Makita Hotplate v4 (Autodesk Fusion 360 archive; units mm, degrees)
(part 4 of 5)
sketch "Sketch1" plane through (0, 0, 0) normal (0, 0, 1) x axis (1, 0, 0)
  line L1 (20, 0) -> (0, 0)
  line L2 (20, 73) -> (20, 0)
  line L3 (0, 73) -> (20, 73)
  line L4 (0, 0) -> (0, 73)
  line L5 (3, 4) -> (3, 69)
  line L6 (0, 36.5) -> (3, 36.5)
  line L7 (0, 69) -> (3, 69)
  line L8 (0, 98) -> (0, 73)
  line L9 (-20, 98) -> (0, 98)
  line L10 (-20, 156) -> (-20, 98)
  line L11 (20, 156) -> (-20, 156)
  line L12 (20, 73) -> (20, 156)
  line L13 (-9, 155.75) -> (-18, 155.75)
  line L14 (-9, 98.25) -> (-9, 155.75)
  line L15 (-18, 98.25) -> (-9, 98.25)
  line L16 (-18, 155.75) -> (-18, 98.25)
  line L17 (-11, 146) -> (-16, 146)
  line L18 (-11, 108) -> (-11, 146)
  line L19 (-16, 108) -> (-11, 108)
  line L20 (-16, 146) -> (-16, 108)
  line L21 (-9, 98.25) -> (-18, 155.75)
  line L22 (-11, 146) -> (-16, 108)
  circle C1 centre (3, 4) radius 1.625
  circle C2 centre (3, 69) radius 1.625
  circle C3 centre (3, 69) radius 3
  circle C4 centre (10, 84.5) radius 5
  point P1 (0, 0)
  point P2 (0, 0)
  point P7 (3, 4)
  point P8 (3, 4)
  point P6 (3, 69)
  point P9 (3, 69)
  point P10 (3, 36.5)
  point P11 (0, 36.5)
  point P12 (3, 69)
  point P13 (0, 69)
  point P14 (1.375, 69)
  point P4 (20, 73)
  point P20 (20, 73)
  point P5 (0, 73)
  point P16 (0, 98)
  point P3 (20, 0)
  point P17 (-20, 98)
  point P18 (-20, 156)
  point P21 (-18, 155.75)
  point P22 (-9, 155.75)
  point P15 (3, 69)
  point P25 (10, 84.5)
  point P26 (-16, 146)
  point P27 (-11, 146)
  point P29 (-16, 108)
  horizontal L1
  vertical L2
  horizontal L3
  vertical L4
  coincident P1 P2
  vertical L5
  coincident P7 P8
  coincident P6 P9
  equal C1 C2
  midpoint L5 P10
  midpoint L4 P11
  horizontal L6
  coincident P9 P12
  coincident L4 P13
  perpendicular L4 L7
  coincident C2 P14
  coincident L7 P14
  concentric C2 C3
  perpendicular L3 L8
  perpendicular L8 L9
  perpendicular L9 L10
  perpendicular L10 L11
  perpendicular L3 L12
  coincident P4 P20
  horizontal L13
  vertical L14
  horizontal L15
  vertical L16
  horizontal L17
  vertical L18
  horizontal L19
  vertical L20
  midpoint L21 L22
  dimension "d1" distance P2 P5 = 73
  dimension "d2" diameter C2 = 3.25
  dimension "d3" distance P6 P7 = 65
  dimension "d4" distance P10 P11 = 3
  dimension "d5" distance L4 P14 = 1.375
  dimension "d6" diameter C3 = 6
  dimension "d13" distance P5 P16 = 25 (= "23.5 mm + 1.5 mm")
  dimension "d14" distance P2 P3 = 20
  dimension "d15" distance P17 P18 = 58
  dimension "d16" distance P16 P17 = 20
  dimension "d17" distance P18 L16 = 2
  dimension "d18" distance P21 P22 = 9
  dimension "d19" distance P18 L13 = 0.25
  dimension "d20" distance P17 L15 = 0.25
  dimension "d21" diameter C4 = 10
  dimension "d22" distance P15 P25 = 15.5
  dimension "d23" distance P15 P25 = 7
  dimension "d24" distance P26 P27 = 5
  dimension "d25" distance P26 P29 = 38
extrude "Extrude1" new body sketch "Sketch1" profile of L1 L2 L4 C1 C2 L8 L9 L10 L11 L12 L13 L14 L15 L16 C4 L17 L18 L19 L20 against normal blind 1.6
extrude "Extrude2" add sketch "Sketch1" profile of L13 L14 L15 L16 L17 L18 L19 L20 along normal blind 25
extrude "Extrude3" add sketch "Sketch1" profile of L17 L18 L19 L20 against normal blind 4.5
component_insert "Component Insert" sketch "Sketch1"
joint "Assemble1" sketch "Sketch1" alignAngle 90 alignOffsetX 0 alignOffsetY 0 alignOffsetZ 0.7
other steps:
joint_origin "JointOrigin2" sketch "Sketch1"

design "M5x25-FHCS"
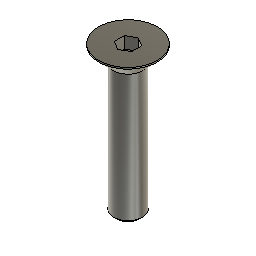
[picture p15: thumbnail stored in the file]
sketch "Sketch1" plane through (0, 0, 0) normal (0, 1, 0) x axis (1, 0, 0)
  line L1 (0, 25) -> (0, 0)
  line L2 (1.95, 25) -> (0, 25)
  line L3 (2.45, 24.5) -> (1.95, 25)
  line L4 (2.45, 2.8) -> (2.45, 24.5)
  line L5 (5, 0.25) -> (2.45, 2.8)
  line L6 (5, 0) -> (5, 0.25)
  line L7 (0, 0) -> (5, 0)
  point P1 (0, 0)
  point P2 (0, 0)
  point P9 (0, 0)
  point P3 (0, 25)
  point P4 (1.95, 25)
  point P8 (5, 0)
  point P7 (5, 0.25)
  coincident P1 P2
  vertical L1
  perpendicular L1 L2
  perpendicular L2 L4
  parallel L3 L5
  parallel L4 L6
  perpendicular L6 L7
  coincident P1 P9
  dimension "d1" distance P3 L4 = 2.45 (= "( 4.9 / 2 ) * 1 mm")
  dimension "d3" angle L2 L3 = 45
  dimension "d5" distance P4 L4 = 0.5
  dimension "d6" distance P2 P3 = 25
  dimension "d7" distance P8 P9 = 5 (= "( 10 / 2 ) * 1 mm")
  dimension "d9" distance P7 P8 = 0.25
revolve "Revolve1" sketch "Sketch1" AlongAngle 360
sketch "Sketch2" plane through (0, 0, 0) normal (0, 0, 1) x axis (-1, 0, 0)
  line L1 (0, -1.7321) -> (-1.5, -0.866)
  line L2 (1.5, -0.866) -> (0, -1.7321)
  line L3 (1.5, 0.866) -> (1.5, -0.866)
  line L4 (0, 1.7321) -> (1.5, 0.866)
  line L5 (-1.5, 0.866) -> (0, 1.7321)
  line L6 (-1.5, -0.866) -> (-1.5, 0.866)
  circle C1 centre (0, 0) radius 5
  point P1 (0, 0)
  point P9 (0, 0)
  coincident P1 P9
  vertical L6
  dimension "d12" distance L3 L6 = 3
extrude "Extrude1" cut sketch "Sketch2" profile of L1 L2 L3 L4 L5 L6 against normal blind 2

design "M4x14-FHCS"
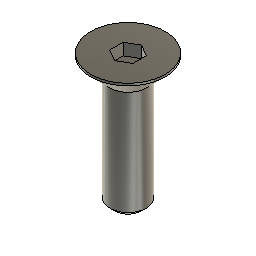
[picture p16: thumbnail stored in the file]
sketch "Sketch1" plane through (0, 0, 0) normal (0, 1, 0) x axis (1, 0, 0)
  line L1 (0, 14) -> (0, 0)
  line L2 (1.45, 14) -> (0, 14)
  line L3 (1.95, 13.5) -> (1.45, 14)
  line L4 (1.95, 2.3) -> (1.95, 13.5)
  line L5 (4, 0.25) -> (1.95, 2.3)
  line L6 (4, 0) -> (4, 0.25)
  line L7 (0, 0) -> (4, 0)
  point P1 (0, 0)
  point P2 (0, 0)
  point P9 (0, 0)
  point P3 (0, 14)
  point P4 (1.45, 14)
  point P8 (4, 0)
  point P7 (4, 0.25)
  coincident P1 P2
  vertical L1
  perpendicular L1 L2
  perpendicular L2 L4
  parallel L3 L5
  parallel L4 L6
  perpendicular L6 L7
  coincident P1 P9
  dimension "d1" distance P3 L4 = 1.95 (= "( 3.9 / 2 ) * 1 mm")
  dimension "d3" angle L2 L3 = 45
  dimension "d5" distance P4 L4 = 0.5
  dimension "d6" distance P2 P3 = 14
  dimension "d7" distance P8 P9 = 4 (= "( 8 / 2 ) * 1 mm")
  dimension "d9" distance P7 P8 = 0.25
revolve "Revolve1" sketch "Sketch1" AlongAngle 360
sketch "Sketch2" plane through (0, 0, 0) normal (0, 0, 1) x axis (-1, 0, 0)
  line L1 (0, -1.4434) -> (-1.25, -0.7217)
  line L2 (1.25, -0.7217) -> (0, -1.4434)
  line L3 (1.25, 0.7217) -> (1.25, -0.7217)
  line L4 (0, 1.4434) -> (1.25, 0.7217)
  line L5 (-1.25, 0.7217) -> (0, 1.4434)
  line L6 (-1.25, -0.7217) -> (-1.25, 0.7217)
  circle C1 centre (0, 0) radius 4
  point P1 (0, 0)
  point P9 (0, 0)
  coincident P1 P9
  vertical L6
  dimension "d12" distance L3 L6 = 2.5
extrude "Extrude1" cut sketch "Sketch2" profile of L1 L2 L3 L4 L5 L6 against normal blind 1.26

design "M5 Nylock"
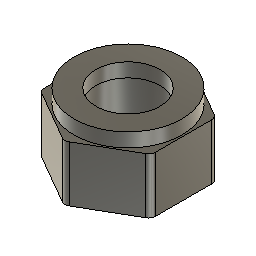
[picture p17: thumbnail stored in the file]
sketch "Sketch1" plane through (0, 0, 0) normal (0, 0, 1) x axis (1, 0, 0)
  line L1 (0, 4.6188) -> (4, 2.3094)
  line L2 (-4, 2.3094) -> (0, 4.6188)
  line L3 (-4, -2.3094) -> (-4, 2.3094)
  line L4 (0, -4.6188) -> (-4, -2.3094)
  line L5 (4, -2.3094) -> (0, -4.6188)
  line L6 (4, 2.3094) -> (4, -2.3094)
  circle C1 centre (0, 0) radius 2.55
  circle C2 centre (0, 0) radius 3.875
  circle C3 centre (0, 0) radius 2.3
  point P1 (0, 0)
  point P8 (0, 0)
  point P9 (0, 0)
  point P4 (-4, 2.3094)
  coincident P1 P8
  vertical L6
  coincident P8 P9
  concentric C1 C2
  concentric C1 C3
  dimension "d1" distance P4 L6 = 8
  dimension "d2" diameter C1 = 5.1
  dimension "d5" diameter C2 = 7.75
  dimension "d9" distance C1 C3 = 0.25
extrude "Extrude1" new body sketch "Sketch1" profile of L1 L2 L3 L4 L5 L6 C1 along normal blind 4
extrude "Extrude2" sketch "Sketch1" profile of C1 C2 C3 blind 1
fillet "Fillet1" radius 0.5

design "Servo Arm 25T"
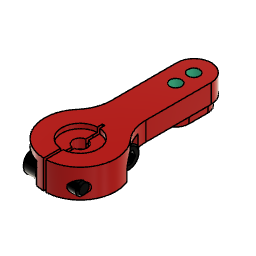
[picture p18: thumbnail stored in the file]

design "M3 Nylock"
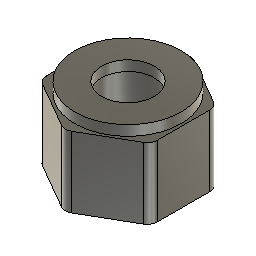
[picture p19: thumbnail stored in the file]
sketch "Sketch1" plane through (0, 0, 0) normal (0, 0, 1) x axis (1, 0, 0)
  line L1 (0, 3.1754) -> (2.75, 1.5877)
  line L2 (-2.75, 1.5877) -> (0, 3.1754)
  line L3 (-2.75, -1.5877) -> (-2.75, 1.5877)
  line L4 (0, -3.1754) -> (-2.75, -1.5877)
  line L5 (2.75, -1.5877) -> (0, -3.1754)
  line L6 (2.75, 1.5877) -> (2.75, -1.5877)
  circle C1 centre (0, 0) radius 1.55
  circle C2 centre (0, 0) radius 2.625
  circle C3 centre (0, 0) radius 1.3
  point P1 (0, 0)
  point P8 (0, 0)
  point P9 (0, 0)
  point P4 (-2.75, 1.5877)
  coincident P1 P8
  vertical L6
  coincident P8 P9
  concentric C1 C2
  concentric C1 C3
  dimension "d1" distance P4 L6 = 5.5
  dimension "d2" diameter C1 = 3.1
  dimension "d5" diameter C2 = 5.25
  dimension "d9" distance C1 C3 = 0.25
extrude "Extrude1" new body sketch "Sketch1" profile of L1 L2 L3 L4 L5 L6 C1 C2 along normal blind 3.5
extrude "Extrude2" sketch "Sketch1" profile of C1 C2 C3 blind 0.5
fillet "Fillet1" radius 0.5

design "Hotplate Pushrod"
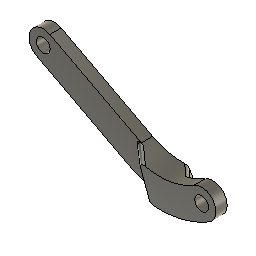
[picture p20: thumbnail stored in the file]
sketch "Sketch1" plane through (0, 0, 0) normal (0, 1, 0) x axis (1, 0, 0)
  line L1 (57.4992, 15.3) -> (0, 0)
  line L2 (43.3571, -7.7) -> (57.4992, 15.3)
  line L3 (43.3571, 19.3) -> (43.3571, -7.7)
  line L4 (30.7869, 16.1954) -> (0, 0)
  line L5 (-2.2347, 4.2481) -> (2.2347, -4.2481)
  line L6 (33.0216, 11.9473) -> (2.2347, -4.2481)
  line L7 (-2.2347, 4.2481) -> (28.5522, 20.4435)
  line L8 (33.0216, 11.9473) -> (28.5522, 20.4435)
  line L9 (35.4522, 23.1018) -> (30.8558, 10.808)
  line L10 (54.6732, 22.0184) -> (49.3571, 13.6738)
  circle C1 centre (0, 0) radius 1.625
  circle C2 centre (57.4992, 15.3) radius 1.625
  arc A1 centre (43.3571, -7.7) radius 27 clockwise from (43.3571, 19.3) to (57.4992, 15.3)
  arc A2 centre (43.3571, -7.7) radius 27 clockwise from (30.7869, 16.1954) to (43.3571, 19.3)
  arc A3 centre (43.3571, -7.7) radius 22.2 clockwise from (33.0216, 11.9473) to (54.9851, 11.2111)
  arc A4 centre (57.4992, 15.3) radius 4.8 clockwise from (60.0134, 19.3889) to (54.9851, 11.2111)
  arc A5 centre (43.3571, -7.7) radius 31.8 clockwise from (28.5522, 20.4435) to (60.0134, 19.3889)
  arc A6 centre (43.3571, -7.7) radius 27 clockwise from (30.7869, 16.1954) to (57.4992, 15.3)
  circle C3 centre (57.4992, 15.3) radius 2.3
  arc A7 centre (0, 0) radius 4.8 clockwise from (2.2347, -4.2481) to (-2.2347, 4.2481)
  circle C4 centre (0, 0) radius 2.3
  point P1 (0, 0)
  point P2 (0, 0)
  point P3 (57.4992, 15.3)
  point P5 (57.4992, 15.3)
  point P4 (0, 0)
  point P7 (57.4992, 15.3)
  point P9 (57.4992, 15.3)
  point P6 (43.3571, -7.7)
  point P10 (43.3571, -7.7)
  point P11 (43.3571, -7.7)
  point P19 (43.3571, -7.7)
  point P12 (30.7869, 16.1954)
  point P17 (30.7869, 16.1954)
  point P21 (0, 0)
  point P28 (54.6732, 22.0184)
  point P27 (49.3571, 13.6738)
  point P26 (35.4522, 23.1018)
  point P25 (30.8558, 10.808)
  point P8 (43.3571, 19.3)
  point P20 (57.4992, 15.3)
  point P24 (0, 0)
  point P16 (28.5522, 20.4435)
  coincident P1 P2
  equal C1 C2
  coincident P3 P5
  coincident P1 P4
  coincident P3 P7
  coincident P5 P9
  coincident P6 P10
  vertical L3
  coincident P6 P11
  tangent A2 L4
  tangent A3 A4
  tangent A4 A5
  coincident P6 P19
  coincident P12 P17
  concentric C2 C3
  coincident P1 P21
  coincident P2 L5
  perpendicular L4 L5
  equal A4 A7
  coincident P17 L8
  perpendicular L4 L8
  concentric C1 C4
  equal C3 C4
  coincident A5 P28
  coincident A3 P27
  coincident A5 P26
  coincident L6 P25
  dimension "d1" diameter C1 = 3.25
  dimension "d2" distance P4 P5 = 59.5 (= "56.5 mm + 3 mm")
  dimension "d6" distance P8 P10 = 27
  dimension "d7" = 31.6
  dimension "d8" diameter C3 = 4.6
  dimension "d9" distance A4 C3 = 2.5
  dimension "d10" distance P20 P24 = 15.3
  dimension "d19" distance P11 P20 = 23
  dimension "d29" angle L3 L10 = 32.5
  dimension "d30" distance L3 P27 = 6
  dimension "d38" distance P16 P26 = 6.9
  dimension "d40" angle L9 L10 = 12
extrude "Extrude4" new body sketch "Sketch1" profile of A3 A4 A5 C3 L9 L10 along normal blind 3.8 bodies "HP Pushrod"
extrude "Extrude5" new body sketch "Sketch1" profile of A3 A5 A7 L6 L7 C4 L9 L10 blind 3.8 from offset 4.2 (= "6.9 mm - 1.2 mm - 1.5 mm")
extrude "Extrude6" add sketch "Sketch1" profile of A3 A5 L6 L7 L9 L10 to an object
chamfer "Chamfer3" distance 4.2
chamfer "Chamfer4" distance 4.2
fillet "Fillet1" radius 1
named bodies: "HP Pushrod"

design "Hotplate Toolchanger" references "M5x25-FHCS", "Servo Standard", "M3x25-FHCS", "Hotplate Tool Template", "6806 Bearing", "PCB Blade Head", "Servo Arm 25T", "3.2x4.5x4mm Unthreaded Spacer", "M3x20-FHCS", "M4x14-FHCS", "M3 Nylock", "Hotplate Pushrod", "M5 Nylock", "M3x14-FHCS", "6x16-Dowel-Pull-Out", "M3 Washer", "M3x10-BHCS", "M3x20-SHCS"
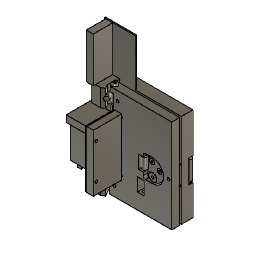
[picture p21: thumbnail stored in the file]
parameter "t_sheet_MAIN" = 7.9375 (= "5 / 16 * 1")
parameter "extrusion_w" = 20
parameter "extrusion_h" = 60
parameter "r_cutoutTool" = 2.05 (= "4.1 mm / 2")
parameter "od_bearings" = 13
parameter "id_bearings" = 4
parameter "t_bearings" = 5
parameter "preload" = 0.15
parameter "hw_m3_thru" = 3.5
parameter "hw_m3_thread" = 2.5
parameter "hw_m3_head" = 5.5
parameter "hw_m3_headheight" = 3
parameter "hw_m3_flathead" = 6
parameter "hw_m3_buttonhead" = 5.7
parameter "hw_m3_washer" = 7
parameter "hw_m3hex_d" = 5.5
parameter "hw_m3hex_t" = 4
parameter "hw_m3i_d" = 5.4
parameter "hw_m3i_l" = 3.8
parameter "hw_m3ichamfer" = 0.95 (= "( hw_m3i_d - hw_m3_thru ) / 2")
parameter "hw_m4_thru" = 4.25
parameter "hw_m4_head" = 7
parameter "hw_m4_headheight" = 4
parameter "hw_m4hex_d" = 7
parameter "hw_m4hex_t" = 5.2
parameter "hw_m4i_d" = 6
parameter "hw_m4i_l" = 4.8
parameter "hw_m4ichamfer" = 0.875 (= "( hw_m4i_d - hw_m4_thru ) / 2")
parameter "hw_m5_thread" = 4.2
parameter "hw_m5_head" = 8.5
parameter "hw_m5_washer" = 10
parameter "hw_m5_thru" = 5.25
parameter "hw_m6_thru" = 6.5
parameter "hw_m6_head" = 10
parameter "hw_m6_flathead" = 12
parameter "hw_m6_buttonhead" = 10.5
parameter "hw_m6_washer" = 12
parameter "p_belt" = 1.4
parameter "w_belt" = 10
parameter "t_belt" = 1.4
parameter "belt_pdo_toothside" = 1.15
parameter "belt_pdo_backside" = 0.25
parameter "t_m4_washer" = 0.85
parameter "flex_t" = 2.54
parameter "flex_l" = 5
parameter "t_motor_plates" = 6 comment "5/16 Phenolic"
parameter "swap_center_distance" = 40
parameter "pd_swap_drive" = 57.2958 (= "( nt_swap_drive * 2 / PI ) * 1 mm")
parameter "pd_swap_pinion" = 10.1859 (= "( nt_swap_pinion * 2 / PI ) * 1 mm")
parameter "od_mintool" = 2.1
parameter "t_sheet_THIN" = 5
parameter "c2c_spanners" = 14
parameter "c2c_height_pts" = 75
parameter "right_int_offset" = 30
parameter "d954" = 1.7
parameter "d1221" = 5
parameter "d1747" = 9
parameter "d1748" = 5.5 (= "t_sheet_THIN + 0.5 mm")
parameter "d1761" = 2
parameter "d1917" = 5
parameter "d2148" = 60
parameter "d2184" = 3
parameter "d2185" = 3 (= "d2184")
parameter "d2474" = 5
sketch "Plan" plane through (0, 0, 0) normal (0, 0, 1) x axis (1, 0, 0)
  line L1 (-35, -5) -> (35, -5)
  line L2 (-35, 5) -> (-35, -5)
  line L3 (35, 5) -> (-35, 5)
  line L4 (35, -5) -> (35, 5)
  line L5 (-32.4254, -7.4282) -> (-37.6216, -10.4282)
  line L6 (-40.4254, 6.4282) -> (-32.4254, -7.4282)
  line L7 (-45.6216, 3.4282) -> (-40.4254, 6.4282)
  line L8 (-37.6216, -10.4282) -> (-45.6216, 3.4282)
  line L9 (-35.0235, -8.9282) -> (-43.0235, 4.9282)
  line L10 (-35, -3.8) -> (-35.5, -3.8)
  line L11 (-35, 3.8) -> (-35.5, 3.8)
  line L12 (-35.5, -3.8) -> (-35.5, 3.8)
  line L13 (-35.5, 0) -> (-35, 0)
  line L14 (0, -5) -> (0, 5)
  line L15 (35, 0) -> (-35, 0)
  line L16 (-30.25, 3) -> (-35, 3)
  line L17 (-30.25, -5) -> (-30.25, 3)
  line L18 (-58.5, 1.7343) -> (-50.3233, -12.4282)
  line L19 (-58.5, 22.2) -> (-58.5, 1.7343)
  line L20 (-35.1895, 7.2) -> (0, 7.2)
  line L21 (-34.9565, -10.0442) -> (-42.4817, 2.9898)
  line L22 (35, 22.2) -> (0, 22.2)
  line L23 (35, 7.2) -> (0, 7.2)
  line L24 (-58.5, 22.2) -> (0, 22.2)
  line L25 (0, 22.2) -> (0, 7.2)
  line L26 (-35.1895, 7.2) -> (-42.4817, 2.9898)
  line L27 (-35, 7.2) -> (-35.1895, 7.2)
  line L28 (-35, 22.2) -> (-35, 7.2)
  line L29 (35, 22.2) -> (35, 7.2)
  line L30 (-39.0857, -12.4282) -> (-34.9565, -10.0442)
  line L31 (-50.3233, -12.4282) -> (-39.0857, -12.4282)
  line L32 (40.7735, -5) -> (35, 5)
  line L33 (7.1213, -2.1213) -> (5, 0)
  line L34 (49, 22.2) -> (35, 22.2)
  line L35 (-36.8, -5) -> (-35, -5)
  line L36 (-36.8, 5) -> (-36.8, -5)
  line L37 (-35, 5) -> (-36.8, 5)
  arc A1 centre (-32.1029, 0) radius 5.0971 clockwise from (-35.5, -3.8) to (-35.5, 3.8)
  circle C1 centre (-33.25, 0) radius 3
  circle C2 centre (5, 0) radius 3
  point P10 (-43.0235, 4.9282)
  point P11 (-35.0235, -8.9282)
  point P15 (-35, -3.8)
  point P16 (-35, 3.8)
  point P14 (-35.5, -3.8)
  point P17 (-35.5, -3.8)
  point P18 (-35, 0)
  point P19 (-35.5, 0)
  point P20 (-37.2, 0)
  point P21 (0, 5)
  point P22 (0, -5)
  point P1 (0, 0)
  point P24 (35, 0)
  point P23 (-33.25, 0)
  point P25 (-35, 3)
  point P27 (-30.25, -5)
  point P28 (-39.0235, -2)
  point P33 (0, 7.2)
  point P36 (0, 7.2)
  point P30 (-58.5, 22.2)
  point P38 (-58.5, 22.2)
  point P31 (-35.1895, 7.2)
  point P39 (-35.1895, 7.2)
  point P41 (-35, 22.2)
  point P4 (-35, 5)
  point P42 (35, 7.2)
  point P5 (35, 5)
  point P37 (35, 7.2)
  point P47 (40.7735, -5)
  point P48 (41.1575, -5.6651)
  point P35 (5, 0)
  point P49 (5, 0)
  point P50 (7.1213, -2.1213)
  point P51 (7.1213, -2.1213)
  point P55 (-35, 5)
  point P3 (-35, -5)
  point P6 (-37.6216, -10.4282)
  point P9 (-45.6216, 3.4282)
  point P8 (-40.4254, 6.4282)
  point P13 (-35.5, 3.8)
  point P34 (0, 22.2)
  point P43 (35, 22.2)
  point P52 (49, 22.2)
  point P54 (-36.8, 5)
  horizontal L1
  vertical L2
  horizontal L3
  vertical L4
  perpendicular L5 L6
  parallel L5 L7
  parallel L6 L8
  midpoint L7 P10
  midpoint L5 P11
  coincident L2 P15
  perpendicular L2 L10
  coincident L2 P16
  perpendicular L2 L11
  perpendicular L11 L12
  coincident P14 P17
  midpoint L2 P18
  perpendicular L2 L13
  midpoint L12 P19
  midpoint A1 P20
  midpoint L3 P21
  midpoint L1 P22
  midpoint P1 L14
  midpoint L4 P24
  coincident P23 L15
  coincident L2 P25
  perpendicular L2 L16
  coincident L1 P27
  perpendicular L1 L17
  midpoint L9 P28
  vertical L19
  horizontal L20
  coincident P33 P36
  coincident P30 P38
  perpendicular L22 L25
  coincident P1 L25
  horizontal L22
  horizontal L23
  horizontal L24
  perpendicular L6 L26
  coincident P31 P39
  parallel L9 L21
  parallel L9 L18
  parallel L20 L27
  coincident L24 P41
  perpendicular L24 L28
  coincident P4 L28
  coincident L23 P42
  perpendicular L22 L29
  coincident P5 L29
  tangent L6 C1
  perpendicular L21 L30
  coincident P37 P42
  coincident L1 P47
  horizontal L31
  parallel L9 L32
  coincident L32 P48
  coincident P35 P49
  coincident C2 P50
  coincident P50 P51
  equal C1 C2
  coincident L15 P35
  perpendicular L29 L34
  perpendicular L2 L35
  perpendicular L35 L36
  perpendicular L36 L37
  coincident P4 P55
  dimension "d1706" distance P3 P4 = 10
  dimension "d1707" distance P6 P9 = 16
  dimension "d1708" distance P8 P9 = 6
  dimension "d1709" distance P13 P17 = 7.6
  dimension "d1710" distance L2 P20 = 2.2
  dimension "d1711" distance P13 P16 = 0.5
  dimension "d1712" distance P1 L2 = 35
  dimension "d1713" diameter C1 = 6
  dimension "d1714" distance L2 P23 = 1.75
  dimension "d1715" distance P23 L17 = 3 (= "d1713 / 2")
  dimension "d1716" distance P23 L16 = 3 (= "d1715")
  dimension "d1717" angle L2 L9 = 30
  dimension "d1723" distance L15 P28 = 2
  dimension "d1740" distance L2 L19 = 23.5
  dimension "d1955" distance L15 L20 = 7.2
  dimension "d1988" distance P33 P34 = 15
  dimension "d1989" distance P4 L26 = 2
  dimension "d1990" distance P28 L18 = 15
  dimension "d2127" distance L3 L20 = 2.2
  dimension "d2158" distance L19 L28 = 23.5
  dimension "d2277" distance P6 L30 = 1
  dimension "d2278" distance P6 L31 = 2
  dimension "d2412" angle L15 L33 = 45
  dimension "d2460" distance P35 L29 = 30 (= "right_int_offset")
  dimension "d2467" distance P43 P52 = 14
  dimension "d2857" distance P54 P55 = 1.8
  dimension "d2858" distance P28 L21 = 0.5
  dimension "d523" OffsetX = 0
  dimension "d524" OffsetY = 0
  dimension "d525" OffsetZ = 0
  dimension "d526" AngleZ = 0
  dimension "d567" OffsetX = 0
  dimension "d568" OffsetY = 0
  dimension "d569" OffsetZ = 0
  dimension "d570" AngleZ = 0
  dimension "d1082" distance = 0.8
  dimension "d1084" distance = 0.8
  dimension "d1085" distance = 1.2
  dimension "d1086" distance = 1.2
  dimension "d1087" distance = 0.1
  dimension "d1093" Radius = 0.5
  dimension "d1095" Radius = 0.5
  dimension "d1097" Radius = 2
  dimension "d1103" distance = 1.3
  dimension "d1105" TotalAngle = 360
  dimension "d1106" distance = 2.75 (= "hw_m3hex_d / 2")
  dimension "d1107" distance = 1.75 (= "hw_m3_thru / 2")
  dimension "d1108" angle = 45
  dimension "d1109" distance = 3.6
  dimension "d1110" distance = 20
  dimension "d1111" distance = 1.7
  dimension "d1113" Side1Offset = 0
  dimension "d1114" TaperAngle = 0
  dimension "d1116" TotalAngle = 360
  dimension "d1118" Radius = 2
  dimension "d1120" distance = 3.175 (= "1 / 8 * 1")
  dimension "d1121" radius = 12
  dimension "d1123" radius = 6.5
  dimension "d1124" angle = 60
  dimension "d1126" distance = 2.8797 (= "13 / 64 * 1  / 2 + 0.3 mm")
  dimension "d1127" distance = 9.5563 (= "7 / 32 * 1  + 4 mm")
  dimension "d1129" diameter = 3.475 (= "1 / 8 * 1  + 0.3 mm")
  dimension "d1130" diameter = 1.7875 (= "1 / 16 * 1  + 0.2 mm")
  dimension "d1143" angle = 51
  dimension "d1144" distance = 2.8797 (= "d1126")
  dimension "d1145" diameter = 1.7875 (= "1 / 16 * 1  + 0.2 mm")
  dimension "d1152" distance = 1.7875 (= "1 / 16 * 1  + 0.2 mm")
  dimension "d1153" Side1Offset = 0
  dimension "d1154" TaperAngle = 0
  dimension "d1155" AlongDistance = -4
  dimension "d1156" TaperAngle = 0
  dimension "d1157" diameter = 5.3594 (= "13 / 64 * 1  + 0.2 mm")
  dimension "d1158" AlongDistance = 1.5
  dimension "d1159" TaperAngle = 0
  dimension "d1169" Radius = 0.4
  dimension "d1170" distance = 11
  dimension "d1171" distance = 1.0938 (= "( 1 / 16 * 1  + 0.2 mm ) / 2 + 0.2 mm")
  dimension "d1172" distance = 1.7
  dimension "d1173" distance = 1.7
  dimension "d1174" Side1Offset = 0
  dimension "d1175" TaperAngle = 0
  dimension "d1176" Side2Offset = -1
  dimension "d1177" Side2TaperAngle = 0
  dimension "d1181" Radius = 0.5
  dimension "d1186" leftDistance = 0.75
  dimension "d1187" rightDistance = 3
  dimension "d1189" Radius = 12
  dimension "d1191" Radius = 2
  dimension "d1193" Radius = 0.5
  dimension "d1195" Radius = 0.5
  dimension "d1197" Radius = 0.5
  dimension "d1202" distance = 13.5
sketch "Elevation" plane through (0, 0, 0) normal (0, 1, 0) x axis (1, 0, 0)
  line L1 (35, 0) -> (-35, 0)
  line L2 (35, -120) -> (35, 0)
  line L3 (-35, -120) -> (35, -120)
  line L4 (-35, 0) -> (-35, -120)
  line L5 (-35, 0) -> (35, 0)
  line L6 (25, -108) -> (-25, -108)
  line L7 (25, -12) -> (25, -108)
  line L8 (-25, -12) -> (25, -12)
  line L9 (-25, -108) -> (-25, -12)
  line L10 (-38, -80.5) -> (-58.5, -80.5)
  line L11 (-38, -39.5) -> (-38, -80.5)
  line L12 (-58.5, -39.5) -> (-38, -39.5)
  line L13 (-43.25, -84.75) -> (-53.25, -84.75)
  line L14 (-43.25, -35.25) -> (-43.25, -84.75)
  line L15 (-53.25, -35.25) -> (-43.25, -35.25)
  line L16 (-53.25, -84.75) -> (-53.25, -35.25)
  line L17 (-48.25, -60) -> (-48.25, -84.75)
  line L18 (-38, -60) -> (-48.25, -60)
  line L19 (-58.5, -97.5) -> (-58.5, -80.5)
  line L20 (-35, -97.5) -> (-58.5, -97.5)
  line L21 (-58.5, -22.5) -> (-35, -22.5)
  line L22 (-58.5, -39.5) -> (-58.5, -22.5)
  line L23 (-50.0746, -84.75) -> (-51.6623, -87.5)
  line L24 (-51.6623, -82) -> (-50.0746, -84.75)
  line L25 (-54.8377, -82) -> (-51.6623, -82)
  line L26 (-56.4254, -84.75) -> (-54.8377, -82)
  line L27 (-54.8377, -87.5) -> (-56.4254, -84.75)
  line L28 (-51.6623, -87.5) -> (-54.8377, -87.5)
  line L29 (-46.4254, -84.75) -> (-44.8377, -82)
  line L30 (-44.8377, -87.5) -> (-46.4254, -84.75)
  line L31 (-41.6623, -87.5) -> (-44.8377, -87.5)
  line L32 (-40.0746, -84.75) -> (-41.6623, -87.5)
  line L33 (-41.6623, -82) -> (-40.0746, -84.75)
  line L34 (-44.8377, -82) -> (-41.6623, -82)
  line L35 (-40.0746, -35.25) -> (-41.6623, -32.5)
  line L36 (-41.6623, -38) -> (-40.0746, -35.25)
  line L37 (-44.8377, -38) -> (-41.6623, -38)
  line L38 (-46.4254, -35.25) -> (-44.8377, -38)
  line L39 (-41.6623, -32.5) -> (-44.8377, -32.5)
  line L40 (-44.8377, -32.5) -> (-46.4254, -35.25)
  line L41 (-54.8377, -38) -> (-51.6623, -38)
  line L42 (-56.4254, -35.25) -> (-54.8377, -38)
  line L43 (-54.8377, -32.5) -> (-56.4254, -35.25)
  line L44 (-51.6623, -32.5) -> (-54.8377, -32.5)
  line L45 (-51.6623, -38) -> (-50.0746, -35.25)
  line L46 (-50.0746, -35.25) -> (-51.6623, -32.5)
  line L47 (-49.25, -85.75) -> (-49.25, -80.5)
  line L48 (-47.25, -80.5) -> (-47.25, -85.75)
  line L49 (-48.25, -85.75) -> (-48.25, -80.5)
  line L50 (-49.25, -34.25) -> (-49.25, -39.5)
  line L51 (-47.25, -39.5) -> (-47.25, -34.25)
  line L52 (-38, -97.5) -> (-38, -80.5)
  line L53 (-38, -22.5) -> (-38, -39.5)
  line L54 (35, -54) -> (-35, -54)
  line L55 (0, 0) -> (0, -120)
  line L56 (25, -64.25) -> (35, -64.25)
  line L57 (25, -43.75) -> (35, -43.75)
  line L58 (25, -28.75) -> (35, -28.75)
  line L59 (25, -79.25) -> (35, -79.25)
  line L60 (30, -64.25) -> (30, -43.75)
  circle C1 centre (-25, -108) radius 2.125
  circle C2 centre (25, -108) radius 2.125
  circle C3 centre (-25, -12) radius 2.125
  circle C4 centre (25, -12) radius 2.125
  circle C5 centre (-25, -108) radius 4
  circle C6 centre (25, -108) radius 4
  circle C7 centre (25, -12) radius 4
  circle C8 centre (-25, -12) radius 4
  circle C9 centre (-53.25, -84.75) radius 1.625
  circle C10 centre (-43.25, -84.75) radius 1.625
  circle C11 centre (-43.25, -35.25) radius 1.625
  circle C12 centre (-53.25, -35.25) radius 1.625
  arc A1 centre (-48.25, -85.75) radius 1 clockwise from (-47.25, -85.75) to (-49.25, -85.75)
  arc A2 centre (-48.25, -80.5) radius 1 clockwise from (-49.25, -80.5) to (-47.25, -80.5)
  arc A3 centre (-48.25, -34.25) radius 1 clockwise from (-49.25, -34.25) to (-47.25, -34.25)
  arc A4 centre (-48.25, -39.5) radius 1 clockwise from (-47.25, -39.5) to (-49.25, -39.5)
  circle C13 centre (0, -27) radius 2.125
  point P2 (-35, 0)
  point P4 (-35, 0)
  point P3 (35, 0)
  point P11 (-25, -108)
  point P15 (-25, -108)
  point P12 (25, -108)
  point P16 (25, -108)
  point P14 (-25, -12)
  point P17 (-25, -12)
  point P13 (25, -12)
  point P18 (25, -12)
  point P1 (0, 0)
  point P23 (0, 0)
  point P32 (-48.25, -84.75)
  point P35 (-43.25, -60)
  point P34 (-38, -60)
  point P36 (-48.25, -80.5)
  point P38 (-35, -97.5)
  point P27 (-58.5, -39.5)
  point P40 (-58.5, -39.5)
  point P28 (-53.25, -84.75)
  point P41 (-53.25, -84.75)
  point P29 (-43.25, -84.75)
  point P42 (-43.25, -84.75)
  point P49 (-53.25, -84.75)
  point P56 (-43.25, -84.75)
  point P43 (-51.6623, -87.5)
  point P68 (-51.6623, -32.5)
  point P44 (-50.0746, -84.75)
  point P69 (-50.0746, -35.25)
  point P45 (-51.6623, -82)
  point P64 (-51.6623, -38)
  point P46 (-54.8377, -82)
  point P65 (-54.8377, -38)
  point P47 (-56.4254, -84.75)
  point P66 (-56.4254, -35.25)
  point P48 (-54.8377, -87.5)
  point P67 (-54.8377, -32.5)
  point P50 (-44.8377, -82)
  point P61 (-44.8377, -38)
  point P51 (-46.4254, -84.75)
  point P62 (-46.4254, -35.25)
  point P52 (-44.8377, -87.5)
  point P63 (-44.8377, -32.5)
  point P53 (-41.6623, -87.5)
  point P58 (-41.6623, -32.5)
  point P54 (-40.0746, -84.75)
  point P59 (-40.0746, -35.25)
  point P55 (-41.6623, -82)
  point P60 (-41.6623, -38)
  point P76 (-48.25, -85.75)
  point P75 (-48.25, -80.5)
  point P71 (-49.25, -80.5)
  point P77 (-49.25, -39.5)
  point P72 (-49.25, -85.75)
  point P78 (-49.25, -34.25)
  point P73 (-47.25, -85.75)
  point P80 (-47.25, -34.25)
  point P74 (-47.25, -80.5)
  point P81 (-47.25, -39.5)
  point P83 (-38, -97.5)
  point P84 (-38, -22.5)
  point P85 (-35, -54)
  point P86 (35, -54)
  point P8 (-35, -22.5)
  point P87 (0, -120)
  point P88 (0, 0)
  point P89 (0, -108)
  point P91 (-58.5, 0)
  point P92 (35, -64.25)
  point P93 (25, -64.25)
  point P94 (35, -43.75)
  point P95 (25, -43.75)
  point P96 (35, -28.75)
  point P97 (25, -28.75)
  point P98 (35, -79.25)
  point P99 (25, -79.25)
  point P100 (30, -43.75)
  point P101 (30, -64.25)
  point P102 (30, -54)
  point P103 (0, -27)
  point P5 (35, 0)
  point P6 (35, -120)
  point P24 (-58.5, -80.5)
  point P25 (-38, -80.5)
  point P26 (-38, -39.5)
  point P31 (-53.25, -35.25)
  point P7 (-35, -120)
  point P21 (25, -12)
  point P37 (-58.5, -97.5)
  point P39 (-58.5, -22.5)
  horizontal L1
  vertical L2
  horizontal L3
  vertical L4
  coincident P2 P4
  coincident P3 L2
  horizontal L6
  vertical L7
  horizontal L8
  vertical L9
  coincident P11 P15
  coincident P12 P16
  coincident P14 P17
  coincident P13 P18
  equal C1 C2
  equal C1 C3
  equal C1 C4
  concentric C1 C5
  concentric C2 C6
  concentric C4 C7
  concentric C3 C8
  equal C5 C8
  equal C5 C6
  equal C5 C7
  coincident P1 P23
  horizontal L10
  perpendicular L10 L11
  perpendicular L11 L12
  horizontal L13
  vertical L14
  horizontal L15
  vertical L16
  midpoint L13 P32
  perpendicular L10 L17
  perpendicular L17 L18
  midpoint L14 P35
  coincident L18 P35
  midpoint L11 P34
  midpoint L10 P36
  coincident L17 P36
  perpendicular L10 L19
  coincident L4 P38
  perpendicular L4 L20
  perpendicular L4 L21
  perpendicular L21 L22
  coincident P27 P40
  coincident L19 P40
  equal L19 L22
  coincident P28 P41
  coincident P29 P42
  equal C9 C10
  coincident P41 P49
  horizontal L28
  coincident P42 P56
  horizontal L31
  equal L28 L31
  symmetric L18 C9 C12
  symmetric L18 C10 C11
  symmetric L18 P43 P68
  symmetric L18 P44 P69
  symmetric L18 P45 P64
  symmetric L18 P46 P65
  symmetric L18 P47 P66
  symmetric L18 P48 P67
  symmetric L18 P50 P61
  symmetric L18 P51 P62
  symmetric L18 P52 P63
  symmetric L18 P53 P58
  symmetric L18 P54 P59
  symmetric L18 P55 P60
  tangent L47 A1
  tangent A1 L48
  parallel L47 L48
  tangent L48 A2
  tangent L47 A2
  coincident L17 P76
  perpendicular L10 L49
  coincident P36 P75
  symmetric L18 P71 P77
  symmetric L18 P72 P78
  symmetric L18 P73 P80
  symmetric L18 P74 P81
  symmetric L18 A1 A3
  symmetric L18 A2 A4
  coincident L20 P83
  perpendicular L20 L52
  coincident L21 P84
  perpendicular L21 L53
  coincident L4 P85
  coincident L2 P86
  perpendicular L2 L54
  coincident L4 P8
  midpoint L3 P87
  coincident P1 P88
  midpoint L6 P89
  coincident L55 P89
  coincident L19 P91
  coincident L2 P92
  coincident L7 P93
  perpendicular L7 L56
  coincident L2 P94
  coincident L7 P95
  perpendicular L7 L57
  coincident L2 P96
  coincident L7 P97
  perpendicular L7 L58
  coincident L2 P98
  coincident L7 P99
  perpendicular L7 L59
  midpoint L57 P100
  midpoint L56 P101
  midpoint L60 P102
  coincident L54 P102
  coincident L55 P103
  dimension "d1741" distance P5 P6 = 120
  dimension "d1938" diameter C1 = 4.25
  dimension "d1940" diameter C5 = 8
  dimension "d2014" distance P24 P25 = 20.5
  dimension "d2015" distance P25 P26 = 41
  dimension "d2016" distance P28 P31 = 49.5
  dimension "d2017" distance P28 P29 = 10
  dimension "d2019" diameter C9 = 3.25
  dimension "d2020" distance P46 L28 = 5.5
  dimension "d2021" distance P72 L48 = 2
  dimension "d2204" distance L13 P76 = 1
  dimension "d2269" distance P4 L18 = 60
  dimension "d2271" distance P11 P12 = 50
  dimension "d2272" distance P12 P13 = 96
  dimension "d2273" distance P1 L8 = 12
  dimension "d2274" distance L3 L6 = 12 (= "d2273")
  dimension "d2275" distance P6 P7 = 70
  dimension "d2279" distance L20 P48 = 10
  dimension "d2295" distance P96 P98 = 50.5
  dimension "d2296" distance P92 P94 = 20.5
  dimension "d2297" distance L59 P101 = 15
  dimension "d2298" distance L58 P100 = 15 (= "d2297")
  dimension "d2336" distance P21 L54 = 42
  dimension "d2337" distance L6 L54 = 54
  dimension "d2338" diameter C13 = 4.25
  dimension "d2339" distance L8 P103 = 15
  dimension "d2748" distance P37 P39 = 75
  dimension "d2749" distance P4 P39 = 22.5
extrude "Extrude179" new body sketch "Plan" profile of L20 L22 L23 L24 L28 L29 to an object
extrude "Extrude180" add sketch "Plan" profile of L21 L18 L19 L20 L24 L26 L27 L28 L30 L31 to an object
extrude "Extrude213" sketch "Plan" profile of L21 L18 L19 L20 L24 L26 L27 L28 L30 L31 to an object
extrude "Extrude185" sketch "Elevation" profile of L10 L12 L19 L20 L21 L22 C9 C10 L23 L24 L25 L26 L27 L28 L29 L30 L31 L32 L33 L34 C11 L35 L36 L37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 blind -23.5
extrude "Extrude245" sketch "Elevation" profile of L4 L11 L20 L21 L52 L53 to an object
sketch "Servo Wall Cleanup" plane through (0, 0, 22.5) normal (0, 0, -1) x axis (1, 0, 0)
  line L1 (-38, -5.5774) -> (-42.4817, -2.9898)
  line L2 (-38, 1.3) -> (-38, -5.5774)
  line L3 (-40.005, 1.3) -> (-38, 1.3)
  line L4 (-42.4817, -2.9898) -> (-40.005, 1.3)
  line L5 (-34.9565, 10.0442) -> (-40.005, 1.3)
  line L6 (-38, 4.7728) -> (-38, 1.3)
  point P4 (-38, 1.3)
  point P8 (-38, 1.3)
  point P9 (-38, 4.7728)
  coincident P4 P8
  coincident L5 P9
  perpendicular L3 L6
extrude "Extrude247" sketch "Servo Wall Cleanup" to an object
extrude "Extrude186" sketch "Elevation" profile of C9 C10 L23 L24 L25 L26 L27 L28 L29 L30 L31 L32 L33 L34 C11 L35 L36 L37 L38 L39 L40 L41 L42 L43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 to an object taper 1 from offset 10
chamfer "Chamfer22" distance 1.5
sketch "Left Pin Mounts" plane through (-11.9151, 20.6375, 0) normal (0.5, -0.866, 0) x axis (0.866, 0.5, 0)
  line L1 (-26.875, 0) -> (-35.2953, 0)
  line L2 (-26.875, 22.5) -> (-26.875, 0)
  line L3 (-34.7953, 12) -> (-34.7953, 0)
  line L4 (-34.7953, 12) -> (-33.7953, 12)
  line L5 (-21.6506, 12) -> (21.6506, 12)
  line L6 (-30.1203, 120) -> (-26.875, 120)
  line L7 (-26.875, 120) -> (-26.875, 97.5)
  line L8 (-26.875, 22.5) -> (-26.875, 97.5)
  line L9 (-33.7953, 60) -> (-26.875, 60)
  line L10 (-34.7953, 108) -> (0, 108)
  line L11 (-30.1203, 97.5) -> (-30.1203, 120)
  line L12 (-30.1203, 22.5) -> (-26.875, 22.5)
  line L13 (-26.875, 97.5) -> (-30.1203, 97.5)
  line L14 (-35.2953, 22.5) -> (-30.1203, 22.5)
  line L15 (-35.2953, 0) -> (-35.2953, 22.5)
  circle C1 centre (-34.7953, 12) radius 3
  circle C2 centre (-34.7953, 12) radius 2.125
  circle C3 centre (-34.7953, 12) radius 4.5
  circle C4 centre (-34.7953, 108) radius 2.125
  circle C5 centre (-34.7953, 108) radius 3
  circle C6 centre (-34.7953, 108) radius 4.5
  point P5 (-34.7953, 0)
  point P6 (-34.7953, 0)
  point P9 (-34.7953, 12)
  point P10 (-34.7953, 12)
  point P7 (-34.7953, 12)
  point P12 (-21.6506, 12)
  point P17 (-26.875, 97.5)
  point P18 (-26.875, 97.5)
  point P2 (-26.875, 22.5)
  point P19 (-26.875, 22.5)
  point P25 (0, 108)
  point P26 (0, 108)
  point P24 (-34.7953, 108)
  point P27 (-34.7953, 108)
  point P20 (-26.875, 60)
  coincident P5 P6
  perpendicular L1 L3
  coincident L3 P9
  perpendicular L3 L4
  coincident P9 P10
  coincident P7 P10
  coincident L4 P12
  concentric C1 C2
  concentric C2 C3
  coincident P17 P18
  coincident P2 P19
  perpendicular L8 L9
  symmetric C1 L9 C5
  symmetric C2 L9 C4
  symmetric C3 L9 C6
  coincident P25 P26
  perpendicular L7 L10
  coincident P24 P27
  coincident L8 P20
  dimension "d1996" diameter C1 = 6
  dimension "d1999" diameter C2 = 4.25
  dimension "d2000" diameter C3 = 9
extrude "Extrude181" sketch "Left Pin Mounts" profile of C1 C2 C4 C5 to an object
extrude "Extrude182" cut sketch "Left Pin Mounts" profile of C2 C4 to an object
extrude "Extrude183" sketch "Left Pin Mounts" profile of C1 C2 C3 C4 C5 C6 to an object from offset -10
chamfer "Chamfer55" distance 3
chamfer "Chamfer41" distance 0.5
chamfer "Chamfer21" distance 2.375 (= "( ( 9 - 4.25 ) / 2 ) * 1 mm")
work_plane "WorkPlane3" AlongDistance 54
sketch "Cam" plane through (0, 0, 54) normal (0, 0, 1) x axis (1, 0, 0)
  line L1 (9.849, 1.1013) -> (5.1263, -3.6213)
  line L2 (6.3279, 7.2) -> (9.849, 1.1013)
  line L3 (7.1213, -2.1213) -> (5, 0)
  line L4 (40.7735, -5) -> (35, 5)
  line L5 (35, 7.2) -> (0, 7.2)
  line L6 (35, 22.2) -> (0, 22.2)
  line L7 (19.5, -3.6213) -> (5.1263, -3.6213)
  line L8 (19.5, 7.2) -> (19.5, -3.6213)
  line L9 (3.45, 7.2) -> (19.5, 7.2)
  line L10 (3.45, 10.2) -> (3.45, 7.2)
  line L11 (4.95, 10.2) -> (3.45, 10.2)
  line L12 (4.95, 11.7) -> (4.95, 10.2)
  line L13 (20, 11.7) -> (4.95, 11.7)
  line L14 (20, 7.2) -> (20, 11.7)
  line L15 (20, 7.2) -> (19.5, 7.2)
  line L16 (12.5756, -3.6213) -> (9.849, 1.1013)
  line L17 (4.95, 17.2) -> (4.95, 12.2)
  line L18 (3.45, 17.2) -> (4.95, 17.2)
  line L19 (3.45, 21.7) -> (3.45, 17.2)
  line L20 (20, 21.7) -> (3.45, 21.7)
  line L21 (20, 12.2) -> (20, 21.7)
  line L22 (4.95, 12.2) -> (20, 12.2)
  line L23 (0.6, 21.95) -> (0.6, 17.2)
  line L24 (-7.9, 21.95) -> (0.6, 21.95)
  line L25 (0.6, 17.2) -> (-7.9, 17.2)
  line L26 (0.6, 10.2) -> (-0.9, 10.2)
  line L27 (0.6, 7.2) -> (0.6, 10.2)
  line L28 (-7.9, 7.2) -> (0.6, 7.2)
  line L29 (-35, -5) -> (35, -5)
  line L30 (-0.9, 16.7) -> (-7.9, 16.7)
  line L31 (-0.9, 10.2) -> (-0.9, 16.7)
  line L32 (-7.9, 17.2) -> (-7.9, 21.95)
  line L33 (-7.9, 7.2) -> (-7.9, 16.7)
  line L34 (10.6263, 21.8787) -> (10.6263, -3.1213)
  line L35 (15.6263, -3.1213) -> (5.6263, -3.1213)
  line L36 (8.1263, 21.7) -> (8.1263, -3.1213)
  line L37 (10.6263, -3.6213) -> (10.6263, -3.1213)
  line L38 (5.3385, -3.6213) -> (9.9266, 0.9668)
  point P20 (20, 7.2)
  point P21 (12.5756, -3.6213)
  point P22 (4.95, 12.2)
  point P28 (4.95, 12.2)
  point P18 (4.95, 11.7)
  point P19 (20, 11.7)
  point P29 (0.6, 17.2)
  point P34 (0.6, 17.2)
  point P24 (3.45, 17.2)
  point P16 (3.45, 10.2)
  point P41 (-7.9, 16.7)
  point P32 (-7.9, 7.2)
  point P37 (-7.9, 7.2)
  point P10 (0, 7.2)
  point P36 (0.6, 7.2)
  point P4 (6.3279, 7.2)
  point P47 (5.6263, -3.1213)
  point P49 (8.4263, -0.3213)
  point P44 (10.6263, -3.1213)
  point P50 (8.1263, -3.1213)
  point P51 (8.1263, 21.7)
  point P52 (10.6263, -3.6213)
  point P53 (9.9266, 0.9668)
  point P54 (5.3385, -3.6213)
  point P17 (4.95, 10.2)
  point P23 (4.95, 17.2)
  point P5 (7.1213, -2.1213)
  point P15 (19.5, 7.2)
  point P38 (5, 0)
  point P14 (19.5, -3.6213)
  point P12 (0, 22.2)
  point P42 (-0.9, 16.7)
  point P27 (20, 12.2)
  point P35 (0.6, 10.2)
  point P45 (10.6263, 21.8787)
  point P1 (0, 0)
  point P31 (-7.9, 21.95)
  point P48 (15.6263, -3.1213)
  point P30 (0.6, 21.95)
  perpendicular L1 L3
  parallel L2 L4
  horizontal L7
  perpendicular L7 L8
  perpendicular L8 L9
  perpendicular L5 L10
  perpendicular L10 L11
  perpendicular L11 L12
  perpendicular L12 L13
  coincident L9 P20
  perpendicular L9 L14
  coincident L7 P21
  parallel L4 L16
  perpendicular L13 L17
  perpendicular L17 L18
  perpendicular L18 L19
  perpendicular L19 L20
  perpendicular L20 L21
  perpendicular L21 L22
  coincident P22 P28
  coincident P18 L17
  coincident P19 L21
  equal L11 L18
  perpendicular L6 L23
  perpendicular L5 L32
  perpendicular L25 L32
  coincident P29 P34
  coincident P24 L25
  horizontal L26
  vertical L27
  horizontal L28
  coincident P16 L26
  coincident P29 L27
  coincident P41 L32
  perpendicular L30 L32
  perpendicular L30 L31
  collinear L32 L33
  horizontal L24
  coincident P32 P37
  coincident P10 L28
  coincident L9 P36
  perpendicular L22 L34
  coincident P4 L9
  coincident L1 P47
  perpendicular L34 L35
  coincident L1 P49
  midpoint P44 L35
  coincident L35 P50
  perpendicular L35 L36
  coincident L20 P51
  coincident L7 P52
  perpendicular L7 L37
  coincident L16 P53
  coincident L7 P54
  parallel L1 L38
  dimension "d2415" distance L12 P19 = 15.05 (= "( 30.1 / 2 ) * 1 mm")
  dimension "d2416" distance P17 P18 = 1.5
  dimension "d2418" distance P16 P17 = 1.5
  dimension "d2423" distance P17 P23 = 7
  dimension "d2424" distance P18 P28 = 0.5
  dimension "d2435" distance L1 P5 = 0.35
  dimension "d2452" distance P15 L14 = 0.5
  dimension "d2471" distance L2 P38 = 4.75
  dimension "d2622" distance P14 L29 = 1.3787
  dimension "d2623" distance L25 L30 = 0.5
  dimension "d2624" distance P12 L20 = 0.5
  dimension "d2625" distance P12 L24 = 0.25
  dimension "d2626" distance L23 P42 = 1.5
  dimension "d2627" distance P27 L31 = 20.9 (= "( 41.8 / 2 ) * 1 mm")
  dimension "d2628" distance P41 L31 = 7
  dimension "d2629" distance P35 P36 = 3
  dimension "d2632" distance P44 P45 = 25
  dimension "d2633" distance L22 P45 = 9.6787
  dimension "d2730" distance P1 L21 = 20
  dimension "d2731" distance P31 P32 = 14.75
  dimension "d2806" distance P47 P48 = 10
  dimension "d2808" distance L35 P49 = 2.8
  dimension "d2809" distance P5 L35 = 1
  dimension "d2810" distance L34 L36 = 2.5
  dimension "d2811" distance L7 P48 = 0.5
  dimension "d2813" distance P49 L38 = 0.15
  dimension "d2833" distance P29 P30 = 4.75
revolve "Revolve3" sketch "Cam" AlongAngle 360 bodies "Rear Cap", "Rotary Cap"
revolve "Revolve4" sketch "Cam" AlongAngle 360
fillet "Fillet104" radius 4
revolve "Revolve6" sketch "Cam" AlongAngle 360
sketch "Cam Cut" plane through (0, 0, 0) normal (1, 0, 0) x axis (0, 1, 0)
  line L1 (7.2, 40.8279) -> (7.2, 67.1721)
  line L2 (-7.8, 58.5118) -> (7.2, 67.1721)
  line L3 (7.2, 66.5947) -> (-7.8, 57.9345)
  line L4 (7.2, 67.1721) -> (-7.8, 71.1913)
  line L5 (-7.8, 57.9345) -> (-7.8, 71.1913)
  line L6 (-7.8, 67.1721) -> (7.2, 67.1721)
  point P2 (7.2, 67.1721)
  point P4 (7.2, 67.1721)
  point P7 (7.2, 66.5947)
  point P9 (7.2, 67.1721)
  point P5 (-7.8, 58.5118)
  point P10 (-7.8, 67.1721)
  coincident P2 P4
  coincident L1 P7
  parallel L2 L3
  coincident P2 P9
  vertical L5
  coincident P5 L5
  coincident L5 P10
  perpendicular L5 L6
  dimension "d2790" distance P9 L5 = 15
  dimension "d2791" angle L2 L4 = 45
  dimension "d2816" angle L2 L6 = 30
  dimension "d2817" distance L2 L3 = 0.5
extrude "Extrude228" cut sketch "Cam Cut" profile of L1 L2 L3 L4 along normal blind 72
chamfer "Chamfer51" distance 1
fillet "Fillet98" radius 3
fillet "Fillet132" radius 0.25
fillet "Fillet133" radius 1
sketch "Sketch80" plane through (0, 21.7, 0) normal (0, 1, 0) x axis (-1, 0, 0)
  line L1 (-10.6263, 49.3812) -> (-14.6263, 51.6906)
  line L2 (-6.6263, 51.6906) -> (-10.6263, 49.3812)
  line L3 (-6.6263, 56.3094) -> (-6.6263, 51.6906)
  line L4 (-10.6263, 58.6188) -> (-6.6263, 56.3094)
  line L5 (-14.6263, 56.3094) -> (-10.6263, 58.6188)
  line L6 (-14.6263, 51.6906) -> (-14.6263, 56.3094)
  circle C1 centre (-10.6263, 54) radius 2.5
  circle C2 centre (-20, 54) radius 16.55
  point P2 (-10.6263, 54)
  point P10 (-10.6263, 54)
  coincident P2 P10
  vertical L6
  dimension "d2823" distance L3 L6 = 8
extrude "Extrude261" cut sketch "Sketch80" profile of C1 L1 L2 L3 L4 L5 L6 against normal blind 5.5
chamfer "Chamfer52" distance 2
sketch "Cam Arm" plane through (0, 7.2, 0) normal (0, -1, 0) x axis (1, 0, 0)
  line L1 (-0.1521, 48.8127) -> (3.6444, 51.4711)
  line L2 (5.5471, 39.1952) -> (9.6321, 41.1001)
  line L3 (-4.1621, 40.05) -> (20, 54)
  line L4 (20, 81.9) -> (20, 54)
  line L5 (-5.8176, 44.8458) -> (-0.1521, 48.8127)
  line L6 (-0.8366, 36.2185) -> (5.5471, 39.1952)
  line L7 (-2.9497, 40.75) -> (-0.8366, 36.2185)
  line L8 (-5.8176, 44.8458) -> (-2.9497, 40.75)
  line L9 (32.8475, 30.8226) -> (20, 54)
  line L10 (28.7023, 28.0266) -> (22.2431, 37.6027)
  line L11 (32.717, 43.4085) -> (37.4152, 32.8563)
  line L12 (32.8475, 30.8226) -> (28.7023, 28.0266)
  line L13 (32.8475, 30.8226) -> (37.4152, 32.8563)
  line L14 (37.8295, 32.5403) -> (34.173, 40.7529)
  line L15 (1.0286, 49.9447) -> (-6.3354, 44.7883)
  line L16 (15.664, 60.1925) -> (1.0286, 49.9447)
  line L17 (20, 54) -> (15.664, 60.1925)
  line L18 (15.7182, 60.2301) -> (20, 54)
  line L19 (-6.4148, 45.0185) -> (15.7182, 60.2301)
  line L20 (0.9412, 50.3775) -> (-6.4974, 45.2651)
  circle C1 centre (20, 54) radius 19.4
  circle C2 centre (-2.9497, 40.75) radius 1.625
  circle C3 centre (-2.9497, 40.75) radius 5.5
  arc A1 centre (-2.9497, 40.75) radius 5 clockwise from (-0.8366, 36.2185) to (-5.8176, 44.8458)
  arc A2 centre (32.8475, 30.8226) radius 5 clockwise from (37.4152, 32.8563) to (28.7023, 28.0266)
  arc A3 centre (20, 54) radius 21.15 clockwise from (5.102, 38.9876) to (-0.4501, 48.6041)
  circle C4 centre (20, 54) radius 27.9
  circle C5 centre (20, 54) radius 20.9
  circle C6 centre (20, 54) radius 16.55
  point P3 (3.6444, 51.4711)
  point P5 (9.6321, 41.1001)
  point P2 (20, 54)
  point P7 (20, 54)
  point P10 (-2.9497, 40.75)
  point P11 (3.1991, 44.3)
  point P12 (-2.9497, 40.75)
  point P15 (-2.9497, 40.75)
  point P16 (-2.9497, 40.75)
  point P17 (20, 54)
  point P41 (20, 54)
  point P18 (32.8475, 30.8226)
  point P19 (32.8475, 30.8226)
  point P22 (22.2431, 37.6027)
  point P23 (32.717, 43.4085)
  point P24 (32.8475, 30.8226)
  point P25 (34.173, 40.7529)
  point P28 (1.0286, 49.9447)
  point P30 (-0.4501, 48.6041)
  point P29 (20, 54)
  point P31 (5.102, 38.9876)
  point P33 (20, 54)
  point P34 (20, 54)
  point P38 (0.9412, 50.3775)
  point P37 (-6.4974, 45.2651)
  point P36 (-6.4148, 45.0185)
  point P27 (-6.3354, 44.7883)
  point P8 (-4.1621, 40.05)
  point P26 (37.8295, 32.5403)
  point P9 (20, 81.9)
  point P40 (-7.2798, 38.25)
  coincident P3 C6
  coincident P5 C6
  coincident P2 P7
  vertical L4
  coincident L3 P10
  coincident C1 P11
  coincident L3 P11
  concentric C2 C3
  parallel L1 L5
  parallel L2 L6
  coincident P12 P15
  coincident P12 P16
  perpendicular L5 L8
  perpendicular L6 L7
  coincident P17 P41
  coincident P18 P19
  equal A1 A2
  coincident P22 C6
  coincident P23 C6
  coincident P19 P24
  perpendicular L10 L12
  perpendicular L11 L13
  coincident C1 P25
  parallel L11 L14
  coincident C1 P28
  coincident L1 P30
  coincident P2 P29
  coincident L2 P31
  parallel L1 L15
  parallel L15 L16
  perpendicular L16 L17
  coincident P7 P33
  coincident P34 P41
  perpendicular L18 L19
  equal L17 L18
  coincident C1 P38
  parallel L19 L20
  coincident P37 C4
  coincident P36 C4
  coincident P27 C4
  coincident P8 C4
  coincident P26 C4
  coincident P9 C4
  midpoint A1 P40
  dimension "d2476" angle L1 L3 = 5
  dimension "d2477" angle L2 L3 = 5 (= "d2476")
  dimension "d2478" angle L3 L4 = 120
  dimension "d2479" diameter C2 = 3.25
  dimension "d2480" distance P7 P10 = 26.5
  dimension "d2481" diameter C3 = 11
  dimension "d2482" radius A1 = 5
  dimension "d2484" distance P17 P18 = 26.5 (= "d2480")
  dimension "d2485" angle L3 L9 = 89
  dimension "d2487" angle L9 L10 = 5
  dimension "d2488" angle L9 L11 = 5
  dimension "d2489" distance L11 L14 = 0.25
  dimension "d2493" distance A3 C5 = 0.25
  dimension "d2512" distance L1 P28 = 0.25
  dimension "d2513" distance L19 L20 = 0.25
  dimension "d2514" angle L16 L19 = 0.5
  dimension "d2736" distance P17 P40 = 31.5
extrude "Extrude229" cut sketch "Cam Arm" profile of C1 L1 L2 L3 C2 L14 A3 C5 L20 C4 to an object
extrude "Extrude230" add sketch "Cam Arm" profile of C1 C6 L1 L2 L3 C2 L5 L6 A1 A3 to an object
extrude "Extrude266" add sketch "Cam Arm" profile of L3 C2 L5 L6 A1 A3 C4 to an object
extrude "Extrude231" sketch "Cam Arm" profile of C1 C6 L1 L2 L3 C2 L5 L6 A1 A3 to an object
fillet "Fillet105" ChordLen 5
extrude "Extrude232" sketch "Cam Arm" profile of L3 C2 L5 L6 A1 A3 C4 to an object offset 4.1
sketch "Cam Arm Hex Insert" plane through (0, 21.7, 0) normal (0, 1, 0) x axis (-1, 0, 0)
  curve K1 (-11.8397, 39.6017) -> (-6.8436, 39.7998)
  line L1 (0.8366, 36.2185) -> (-6.8436, 39.7998)
  line L2 (-1.1241, 49.7064) -> (5.8176, 44.8458)
  curve K2 (-1.1241, 49.7064) -> (-3.4505, 54.1322)
  line L3 (4.5374, 43.5) -> (6.1251, 40.75)
  line L4 (1.362, 43.5) -> (4.5374, 43.5)
  line L5 (-0.2258, 40.75) -> (1.362, 43.5)
  line L6 (1.362, 38) -> (-0.2258, 40.75)
  line L7 (4.5374, 38) -> (1.362, 38)
  line L8 (6.1251, 40.75) -> (4.5374, 38)
  line L9 (-20, 54) -> (2.9497, 40.75)
  line L10 (-14.6263, 51.6906) -> (-10.6263, 49.3812)
  line L11 (-14.6263, 56.3094) -> (-14.6263, 51.6906)
  line L12 (-10.6263, 58.6188) -> (-14.6263, 56.3094)
  line L13 (-6.6263, 56.3094) -> (-10.6263, 58.6188)
  line L14 (-6.6263, 51.6906) -> (-6.6263, 56.3094)
  line L15 (-10.6263, 49.3812) -> (-6.6263, 51.6906)
  circle C1 centre (2.9497, 40.75) radius 1.625
  arc A1 centre (-20, 54) radius 16.55 clockwise from (-11.8397, 39.6017) to (-3.4505, 54.1322)
  arc A2 centre (2.9497, 40.75) radius 5 clockwise from (5.8176, 44.8458) to (0.8366, 36.2185)
  point P2 (2.9497, 40.75)
  point P16 (2.9497, 40.75)
  point P17 (2.9497, 40.75)
  point P5 (-20, 54)
  point P18 (-20, 54)
  point P12 (1.362, 43.5)
  coincident P2 P16
  coincident P2 P17
  coincident P5 P18
  perpendicular L5 L9
  dimension "d2527" distance P12 L8 = 5.5
extrude "Extrude233" cut sketch "Cam Arm Hex Insert" profile of C1 L3 L4 L5 L6 L7 L8 against normal blind 5
chamfer "Chamfer30" distance 1.25
fillet "Fillet124" radius 1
